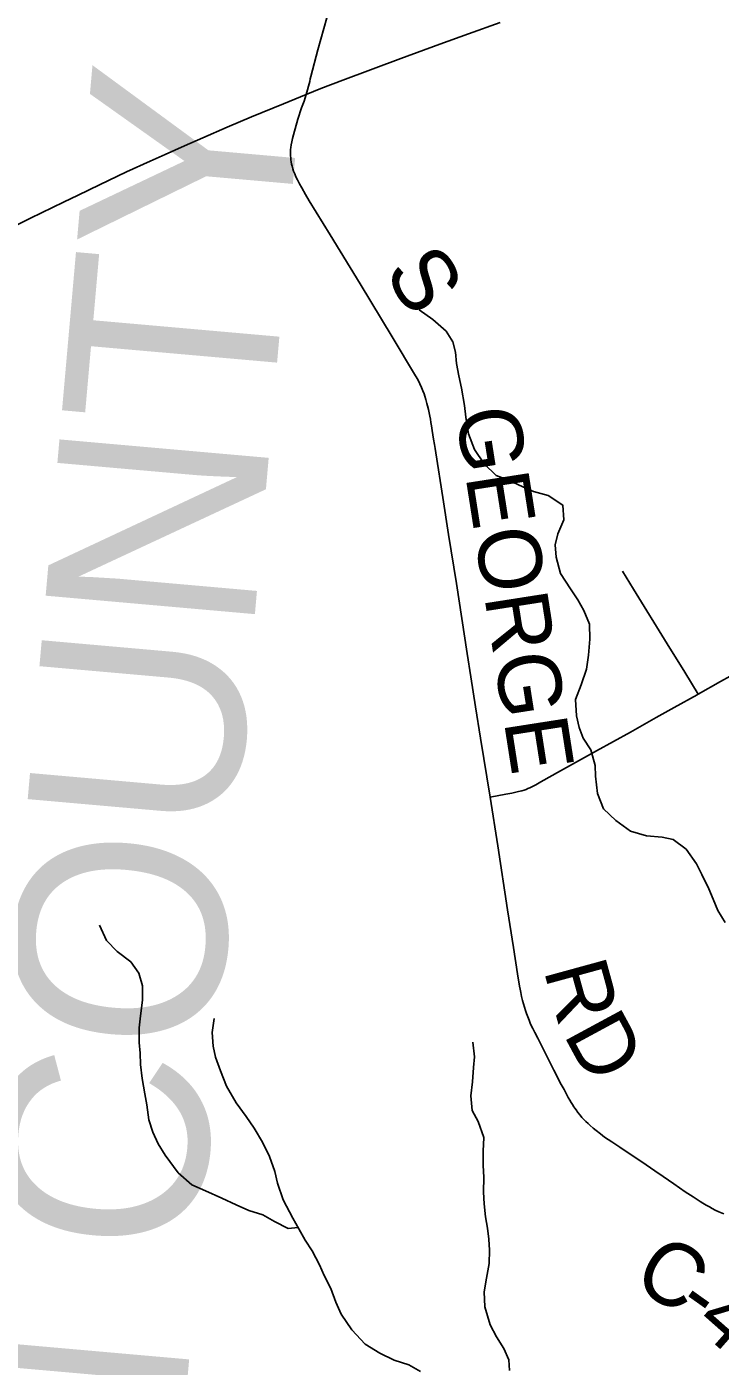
# Model space of a CAD drawing. Extents: x 0 to 34, y 0 to 22.
# Drawn here: x 18.328 to 18.953, y 19.518 to 20.726 of the extents above; entities that cross this region are included whole.
import ezdxf

# ---------------------------------------------------------------- set-up
doc = ezdxf.new("R2010")
doc.units = 0
for name, color, linetype in [('GM_X_County_Road', 7, 'Continuous'), ('GM_X_County_Road_Text', 7, 'Continuous'), ('GM_X_County_Text', 7, 'Continuous'), ('GM_X_Minor_River', 7, 'Continuous'), ('GM_X_State_Route', 7, 'Continuous'), ('GM_X_Township_Road', 7, 'Continuous'), ('GM_X_US_Route', 7, 'Continuous')]:
    doc.layers.add(name, color=color, linetype=linetype)

msp = doc.modelspace()

# ---------------------------------------------------------------- linework, layer by layer
at = {"layer": 'GM_X_County_Road'}
for points in [[(18.5798, 20.665), (18.5829, 20.6767), (18.5834, 20.679), (18.584, 20.6813), (18.5903, 20.7053), (18.6038, 20.7535), (18.6078, 20.7675), (18.6113, 20.7799), (18.6163, 20.797), (18.6315, 20.8499), (18.6368, 20.8685), (18.6388, 20.8756), (18.6405, 20.8824), (18.6415, 20.8864), (18.6422, 20.8899), (18.6425, 20.8931), (18.6427, 20.8959), (18.6426, 20.8981), (18.6424, 20.9009), (18.6419, 20.9039), (18.6413, 20.9067), (18.6405, 20.9092), (18.6398, 20.9111)], [(18.7456, 20.0315), (18.737, 20.0846), (18.7325, 20.113), (18.7283, 20.1399), (18.7249, 20.161), (18.7151, 20.2242), (18.7081, 20.2683), (18.7029, 20.3015), (18.6965, 20.342), (18.6959, 20.3458), (18.6953, 20.3494), (18.6946, 20.3542), (18.694, 20.358), (18.6933, 20.362), (18.6927, 20.3663), (18.6922, 20.3693), (18.6917, 20.3723), (18.6912, 20.3749), (18.6906, 20.3779), (18.69, 20.3808), (18.6891, 20.3842), (18.6886, 20.3864), (18.6877, 20.3899), (18.6867, 20.393), (18.686, 20.3951), (18.6849, 20.3979), (18.6837, 20.4009), (18.6822, 20.404), (18.6803, 20.4079), (18.6784, 20.4113), (18.6573, 20.4465), (18.6284, 20.4944), (18.6012, 20.5383), (18.5825, 20.5692), (18.5792, 20.5748), (18.5758, 20.5808), (18.5738, 20.5845), (18.5719, 20.588), (18.5708, 20.5901), (18.5702, 20.5916), (18.5694, 20.5934), (18.5684, 20.5958), (18.5677, 20.5979), (18.5671, 20.6002), (18.5666, 20.6022), (18.5662, 20.6042), (18.5659, 20.606), (18.5658, 20.608), (18.5657, 20.6097), (18.5656, 20.6119), (18.5657, 20.6137), (18.5657, 20.6154), (18.5659, 20.6173), (18.5662, 20.6196), (18.5667, 20.6223), (18.5674, 20.6252), (18.5682, 20.6286), (18.5723, 20.6426), (18.5756, 20.653), (18.5778, 20.6591), (18.5798, 20.665)], [(18.9563, 19.6556), (18.9517, 19.6576), (18.9486, 19.6591), (18.9458, 19.6605), (18.9432, 19.6619), (18.9402, 19.6635), (18.9373, 19.6653), (18.9348, 19.6668), (18.9285, 19.6709), (18.9215, 19.6756), (18.9113, 19.6827), (18.9016, 19.6893), (18.894, 19.6945), (18.8861, 19.6999), (18.8624, 19.7157), (18.8554, 19.7205), (18.8488, 19.7249), (18.8452, 19.7277), (18.8411, 19.7308), (18.8384, 19.733), (18.8357, 19.7354), (18.8338, 19.7372), (18.8318, 19.7391), (18.8301, 19.7408), (18.8283, 19.7427), (18.8266, 19.7448), (18.8246, 19.7472), (18.8231, 19.7494), (18.8219, 19.751), (18.821, 19.7523), (18.8198, 19.7542), (18.8186, 19.7561), (18.8175, 19.7581), (18.816, 19.7607), (18.8144, 19.7637), (18.8122, 19.7677), (18.8097, 19.7722), (18.803, 19.7851), (18.7885, 19.814), (18.7858, 19.8192), (18.784, 19.8228), (18.783, 19.825), (18.7818, 19.8277), (18.7807, 19.8303), (18.7794, 19.8334), (18.7783, 19.8362), (18.7774, 19.8389), (18.7764, 19.842), (18.7755, 19.845), (18.7746, 19.8481), (18.7738, 19.8516), (18.7731, 19.8552), (18.7725, 19.8582), (18.772, 19.8611), (18.7702, 19.8721), (18.7665, 19.896), (18.7612, 19.9297), (18.7525, 19.9875), (18.7456, 20.0315)]]:
    msp.add_lwpolyline(points, dxfattribs=at)
at = {"layer": 'GM_X_Minor_River'}
for points in [[(18.798, 20.3034), (18.7848, 20.3071), (18.775, 20.3111), (18.7615, 20.3174), (18.751, 20.3214), (18.7402, 20.3319), (18.7314, 20.3449), (18.726, 20.3591), (18.7237, 20.3739), (18.7224, 20.3846), (18.7196, 20.4002), (18.7172, 20.4112), (18.7152, 20.4223), (18.7142, 20.4326), (18.7118, 20.4421), (18.7059, 20.4517), (18.694, 20.4622), (18.6817, 20.4708)], [(18.9576, 19.9185), (18.951, 19.9293), (18.9466, 19.9393), (18.9426, 19.9488), (18.9365, 19.9618), (18.9317, 19.9714), (18.9222, 19.9845), (18.9106, 19.9931), (18.9008, 19.9952), (18.8864, 19.9966), (18.8721, 20.0007), (18.859, 20.0104), (18.8479, 20.0209), (18.8425, 20.0346), (18.8405, 20.0502), (18.8404, 20.0601), (18.8365, 20.0742), (18.8295, 20.0846), (18.8259, 20.0942), (18.8235, 20.1048), (18.8226, 20.1196), (18.8275, 20.1328), (18.8323, 20.1468), (18.8341, 20.1593), (18.8355, 20.174), (18.835, 20.1873), (18.83, 20.1996), (18.8245, 20.2092), (18.8179, 20.2192), (18.809, 20.233), (18.8052, 20.2479), (18.8043, 20.2589), (18.8067, 20.2687), (18.8119, 20.2815), (18.8111, 20.2948), (18.798, 20.3034)], [(18.5724, 19.6435), (18.5636, 19.6425), (18.5512, 19.6488), (18.5407, 19.6547), (18.5279, 19.6588), (18.5167, 19.6639), (18.5035, 19.6699), (18.4889, 19.6763), (18.4765, 19.6818), (18.4642, 19.6927), (18.4524, 19.7085), (18.4462, 19.7188), (18.4415, 19.7292), (18.4379, 19.7406), (18.4359, 19.7539), (18.4342, 19.7638), (18.4319, 19.7776), (18.4302, 19.7905), (18.4301, 19.8007), (18.4291, 19.8102), (18.429, 19.8235), (18.4304, 19.8341), (18.4322, 19.8485), (18.4321, 19.8614), (18.4289, 19.8728), (18.4215, 19.8829), (18.4092, 19.8922), (18.3996, 19.9023), (18.3934, 19.916)], [(18.6829, 19.5135), (18.6721, 19.5197), (18.6589, 19.5238), (18.6461, 19.5301), (18.633, 19.5383), (18.6208, 19.5511), (18.6112, 19.5653), (18.6065, 19.576), (18.6019, 19.5883), (18.596, 19.6002), (18.5917, 19.6097), (18.5851, 19.6224), (18.5789, 19.632), (18.573, 19.6423), (18.5676, 19.6519), (18.5588, 19.6684), (18.5538, 19.6833), (18.5514, 19.694), (18.5467, 19.7074), (18.5402, 19.7204), (18.5329, 19.7331), (18.5255, 19.7435), (18.5167, 19.7558), (18.5079, 19.7707), (18.5025, 19.7845), (18.4978, 19.7971), (18.4957, 19.807), (18.4948, 19.8192), (18.4966, 19.8317)], [(18.7629, 19.5145), (18.7623, 19.524), (18.758, 19.5344), (18.7514, 19.5447), (18.7455, 19.5555), (18.7409, 19.5719), (18.7401, 19.5855), (18.7422, 19.5976), (18.7448, 19.6109), (18.745, 19.623), (18.7445, 19.6329), (18.7432, 19.6428), (18.7415, 19.6531), (18.7402, 19.6648), (18.7397, 19.6751), (18.7399, 19.6887), (18.7394, 19.6994), (18.7393, 19.7123), (18.7399, 19.7244), (18.7349, 19.7389), (18.7294, 19.7489), (18.7282, 19.7622), (18.7296, 19.7747), (18.7306, 19.7876), (18.7316, 19.7974), (18.7299, 19.8104)]]:
    msp.add_lwpolyline(points, dxfattribs=at)
at = {"layer": 'GM_X_State_Route'}
for points in [[(18.5798, 20.665), (18.593, 20.6703), (18.6127, 20.6779), (18.665, 20.6974), (18.7003, 20.7103), (18.726, 20.7196), (18.7546, 20.7299)], [(18.1734, 20.4691), (18.1842, 20.4752), (18.2117, 20.4907), (18.2526, 20.5129), (18.2663, 20.5202), (18.2809, 20.5279), (18.3095, 20.5425), (18.3312, 20.5534), (18.3609, 20.568), (18.374, 20.5743), (18.3932, 20.5836), (18.4178, 20.5952), (18.439, 20.6049), (18.4526, 20.611), (18.47, 20.6187), (18.4865, 20.6259), (18.5086, 20.6355), (18.5303, 20.6447), (18.5593, 20.6566), (18.5798, 20.665)]]:
    msp.add_lwpolyline(points, dxfattribs=at)
at = {"layer": 'GM_X_Township_Road'}
for points in [[(18.9332, 20.1244), (18.9211, 20.1442), (18.9051, 20.1698), (18.8748, 20.2189), (18.8648, 20.2353)], [(18.9332, 20.1244), (18.9533, 20.1356), (18.9793, 20.1501)], [(18.7456, 20.0315), (18.7596, 20.0341), (18.765, 20.0351), (18.7686, 20.0358), (18.7711, 20.0364), (18.774, 20.0371), (18.7761, 20.0378), (18.7779, 20.0384), (18.7796, 20.0391), (18.7814, 20.0399), (18.7838, 20.0411), (18.7867, 20.0426), (18.7913, 20.0453), (18.8089, 20.0551), (18.8416, 20.0733), (18.872, 20.0901), (18.8953, 20.1031), (18.9116, 20.1122), (18.9321, 20.1238), (18.9332, 20.1244)]]:
    msp.add_lwpolyline(points, dxfattribs=at)
at = {"layer": 'GM_X_US_Route'}
for points in [[(18.5798, 20.665), (18.593, 20.6703), (18.6127, 20.6779), (18.665, 20.6974), (18.7003, 20.7103), (18.726, 20.7196), (18.7546, 20.7299)], [(18.1734, 20.4691), (18.1842, 20.4752), (18.2117, 20.4907), (18.2526, 20.5129), (18.2663, 20.5202), (18.2809, 20.5279), (18.3095, 20.5425), (18.3312, 20.5534), (18.3609, 20.568), (18.374, 20.5743), (18.3932, 20.5836), (18.4178, 20.5952), (18.439, 20.6049), (18.4526, 20.611), (18.47, 20.6187), (18.4865, 20.6259), (18.5086, 20.6355), (18.5303, 20.6447), (18.5593, 20.6566), (18.5798, 20.665)]]:
    msp.add_lwpolyline(points, dxfattribs=at)

# ---------------------------------------------------------------- texts
at = {"layer": 'GM_X_County_Road_Text'}
for s, height, rotation, p in [('S', 0.0568, 301.6067, (18.6492, 20.5052)), ('GEORGE', 0.05682, 278.8981, (18.7141, 20.3793)), ('R', 0.0568, 285.3313, (18.7936, 19.8758)), ('D', 0.0568, 298.4039, (18.8111, 19.8179)), ('C', 0.0568, 328.0151, (18.8719, 19.5922)), ('-', 0.0568, 324.5581, (18.9107, 19.568)), ('4', 0.0568, 318.5385, (18.9285, 19.5554))]:
    msp.add_text(s, height=height, rotation=rotation, dxfattribs=at).set_placement(p)
at = {"layer": 'GM_X_County_Text'}
msp.add_text('CLINTON COUNTY', height=0.189394, rotation=84.9582, dxfattribs=at).set_placement((18.3783, 18.4377))

doc.saveas('drawing.dxf')
